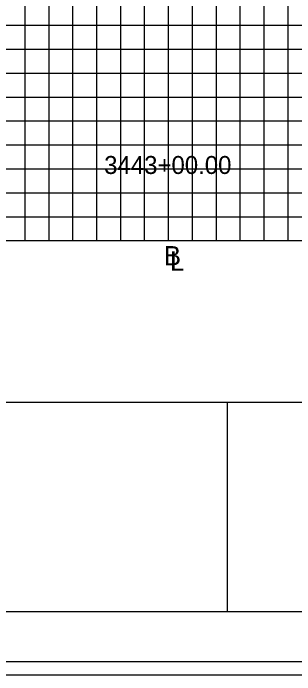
# Model space of a CAD drawing. Extents: x 967 to 1326, y 964 to 3704.
# Drawn here: x 1147 to 1170.6, y 1243.7 to 1299 of the extents above; entities that cross this region are included whole.
import ezdxf

# ---------------------------------------------------------------- set-up
doc = ezdxf.new("R2010")
doc.units = 0
for name, color, linetype in [('Default', 7, 'Continuous'), ('RD_SHT_Bndy', 7, 'Continuous'), ('RD_SHT_IplotShp', 7, 'Continuous'), ('RD_SHT_MjGrid', 7, 'Continuous'), ('RD_SHT_MnGrid', 7, 'Continuous'), ('RD_SHT_TX', 7, 'Continuous'), ('RD_XS_TX_Station', 7, 'Continuous')]:
    doc.layers.add(name, color=color, linetype=linetype)

msp = doc.modelspace()

# ---------------------------------------------------------------- linework, layer by layer
at = {"layer": 'RD_SHT_Bndy'}
for p, q in [((996.114, 1266.486), (1323.886, 1266.486)), ((1164.932, 1248.983), (1164.932, 1266.526)), ((1323.886, 1248.983), (996.114, 1248.983))]:
    msp.add_line(p, q, dxfattribs=at)
at = {"layer": 'RD_SHT_IplotShp'}
for points in [[(967.409, 1243.72), (1326.285, 1243.72), (1326.285, 1463.72), (967.409, 1463.72)], [(988.525, 1244.84), (1326.285, 1244.84), (1326.285, 1462.6), (988.525, 1462.6)]]:
    msp.add_lwpolyline(points, close=True, dxfattribs=at)
at = {"layer": 'RD_SHT_MjGrid'}
for p, q in [((1150, 1280), (1150, 1450)), ((1160, 1280), (1160, 1450)), ((1170, 1280), (1170, 1450)), ((1000, 1290), (1320, 1290)), ((1000, 1280), (1320, 1280))]:
    msp.add_line(p, q, dxfattribs=at)
at = {"layer": 'RD_SHT_MnGrid'}
for p, q in [((1148, 1280), (1148, 1450)), ((1152, 1280), (1152, 1450)), ((1154, 1280), (1154, 1450)), ((1156, 1280), (1156, 1450)), ((1158, 1280), (1158, 1450)), ((1162, 1280), (1162, 1450)), ((1164, 1280), (1164, 1450)), ((1166, 1280), (1166, 1450)), ((1168, 1280), (1168, 1450)), ((1000, 1298), (1320, 1298)), ((1000, 1296), (1320, 1296)), ((1000, 1294), (1320, 1294)), ((1000, 1292), (1320, 1292)), ((1000, 1288), (1320, 1288)), ((1000, 1286), (1320, 1286)), ((1000, 1284), (1320, 1284)), ((1000, 1282), (1320, 1282))]:
    msp.add_line(p, q, dxfattribs=at)
at = {"layer": 'RD_XS_TX_Station'}
msp.add_lwpolyline([(967.409, 1243.72), (1326.285, 1243.72), (1326.285, 1463.72), (967.409, 1463.72)], close=True, dxfattribs=at)

# ---------------------------------------------------------------- texts
at = {"layer": 'Default'}
msp.add_text('3443+00.00', height=1.5, dxfattribs=at).set_placement((1154.611, 1285.568))
at = {"layer": 'RD_SHT_TX'}
for s, p in [('B', (1159.615, 1277.941)), ('L', (1160.124, 1277.491))]:
    msp.add_text(s, height=1.6, dxfattribs=at).set_placement(p)

doc.saveas('drawing.dxf')
